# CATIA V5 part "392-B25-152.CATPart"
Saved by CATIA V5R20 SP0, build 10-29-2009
Part number: 392-B25-152
Definition: NONE
Nomenclature: 392-B25-152
Source: Unknown
Description: 392-B25-152
Bounding box of the stored display mesh (mm): x 0 to 152, y -12.353 to 12.353, z -12.064 to 12.064
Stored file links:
  C:\Users\Utente\Desktop\IO LAVORO\3D X SITO CF\X SITO\3D files 392B\392-B25-152.CATPart
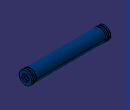
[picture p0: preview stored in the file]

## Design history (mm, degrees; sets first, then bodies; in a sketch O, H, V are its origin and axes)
Body1 "392-B25-152" (main body)
  Solid1: solid without history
